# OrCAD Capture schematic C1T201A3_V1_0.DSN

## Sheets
1 002_POWER: size A; rev: V1.0; note: C1T201A3
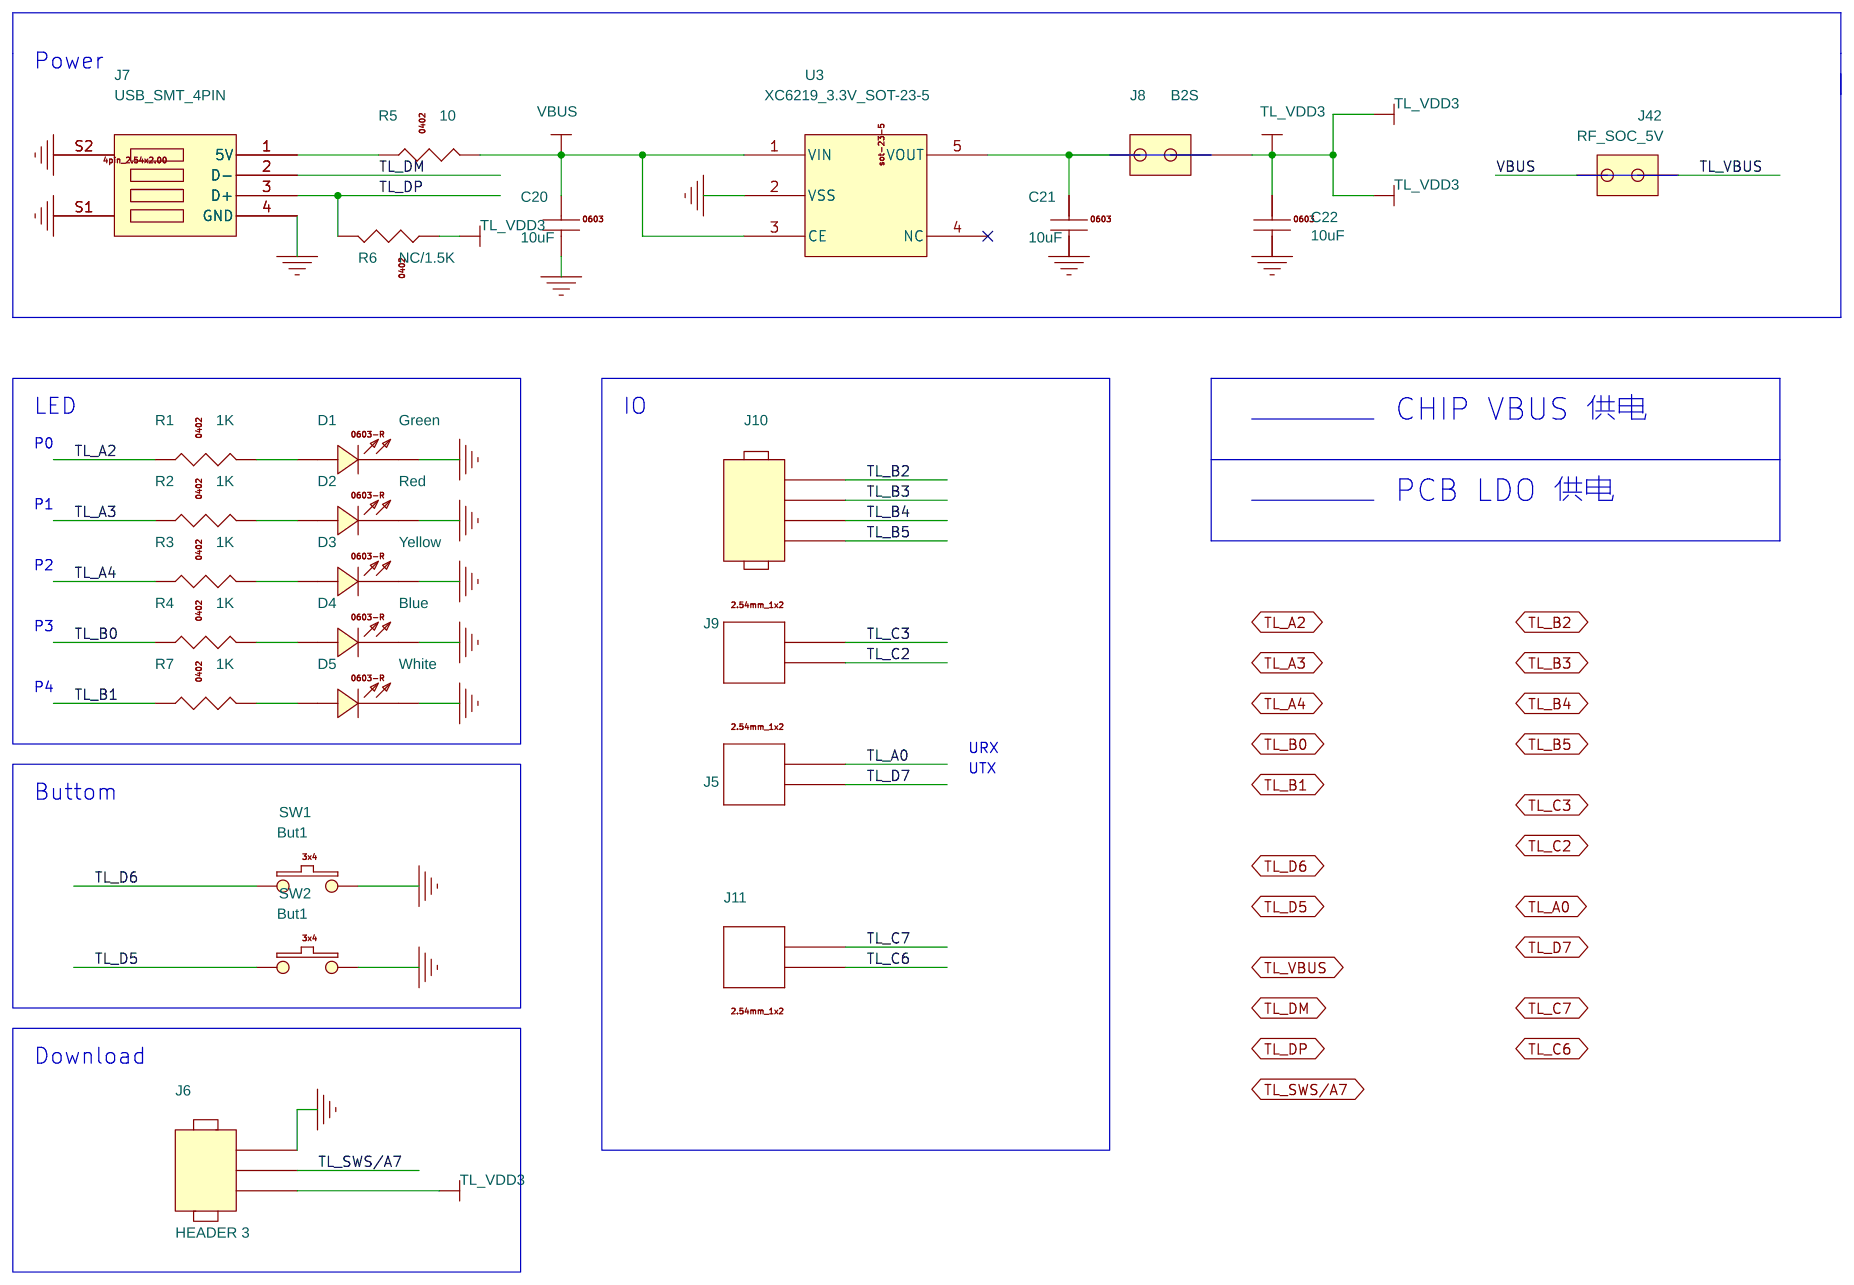
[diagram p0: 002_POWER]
2 000_NOTE: title: Telink-Semi
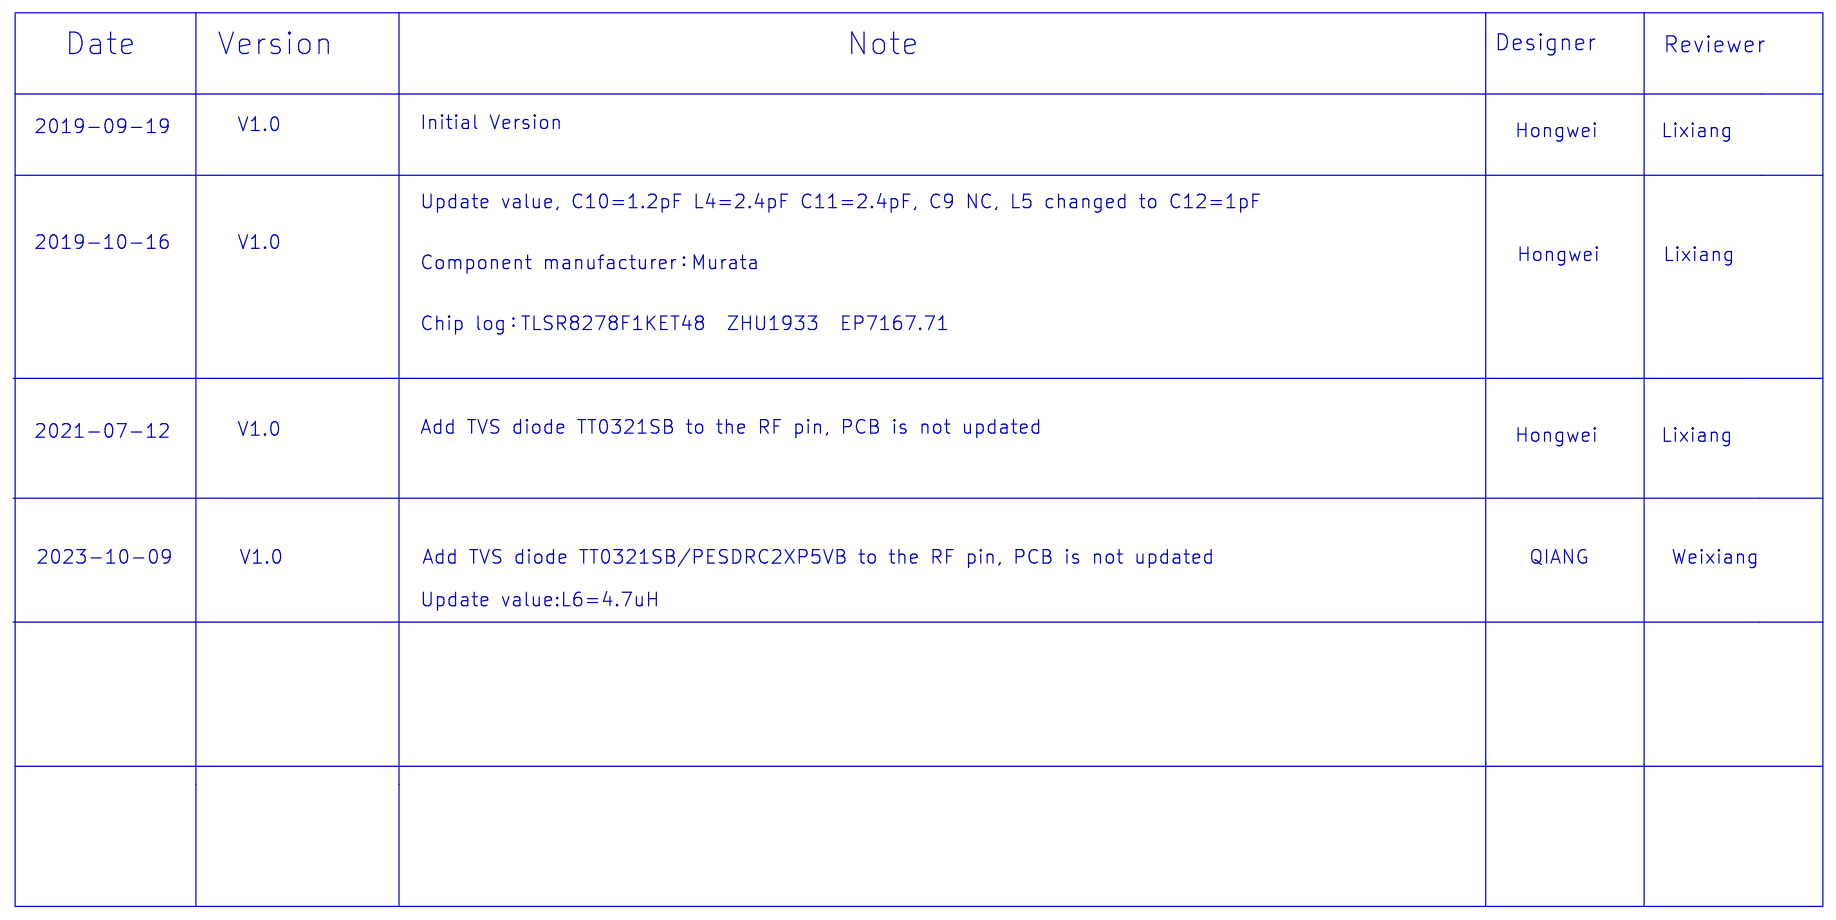
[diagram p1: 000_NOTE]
3 001_MAIN: size A4; title: Telink-Semi
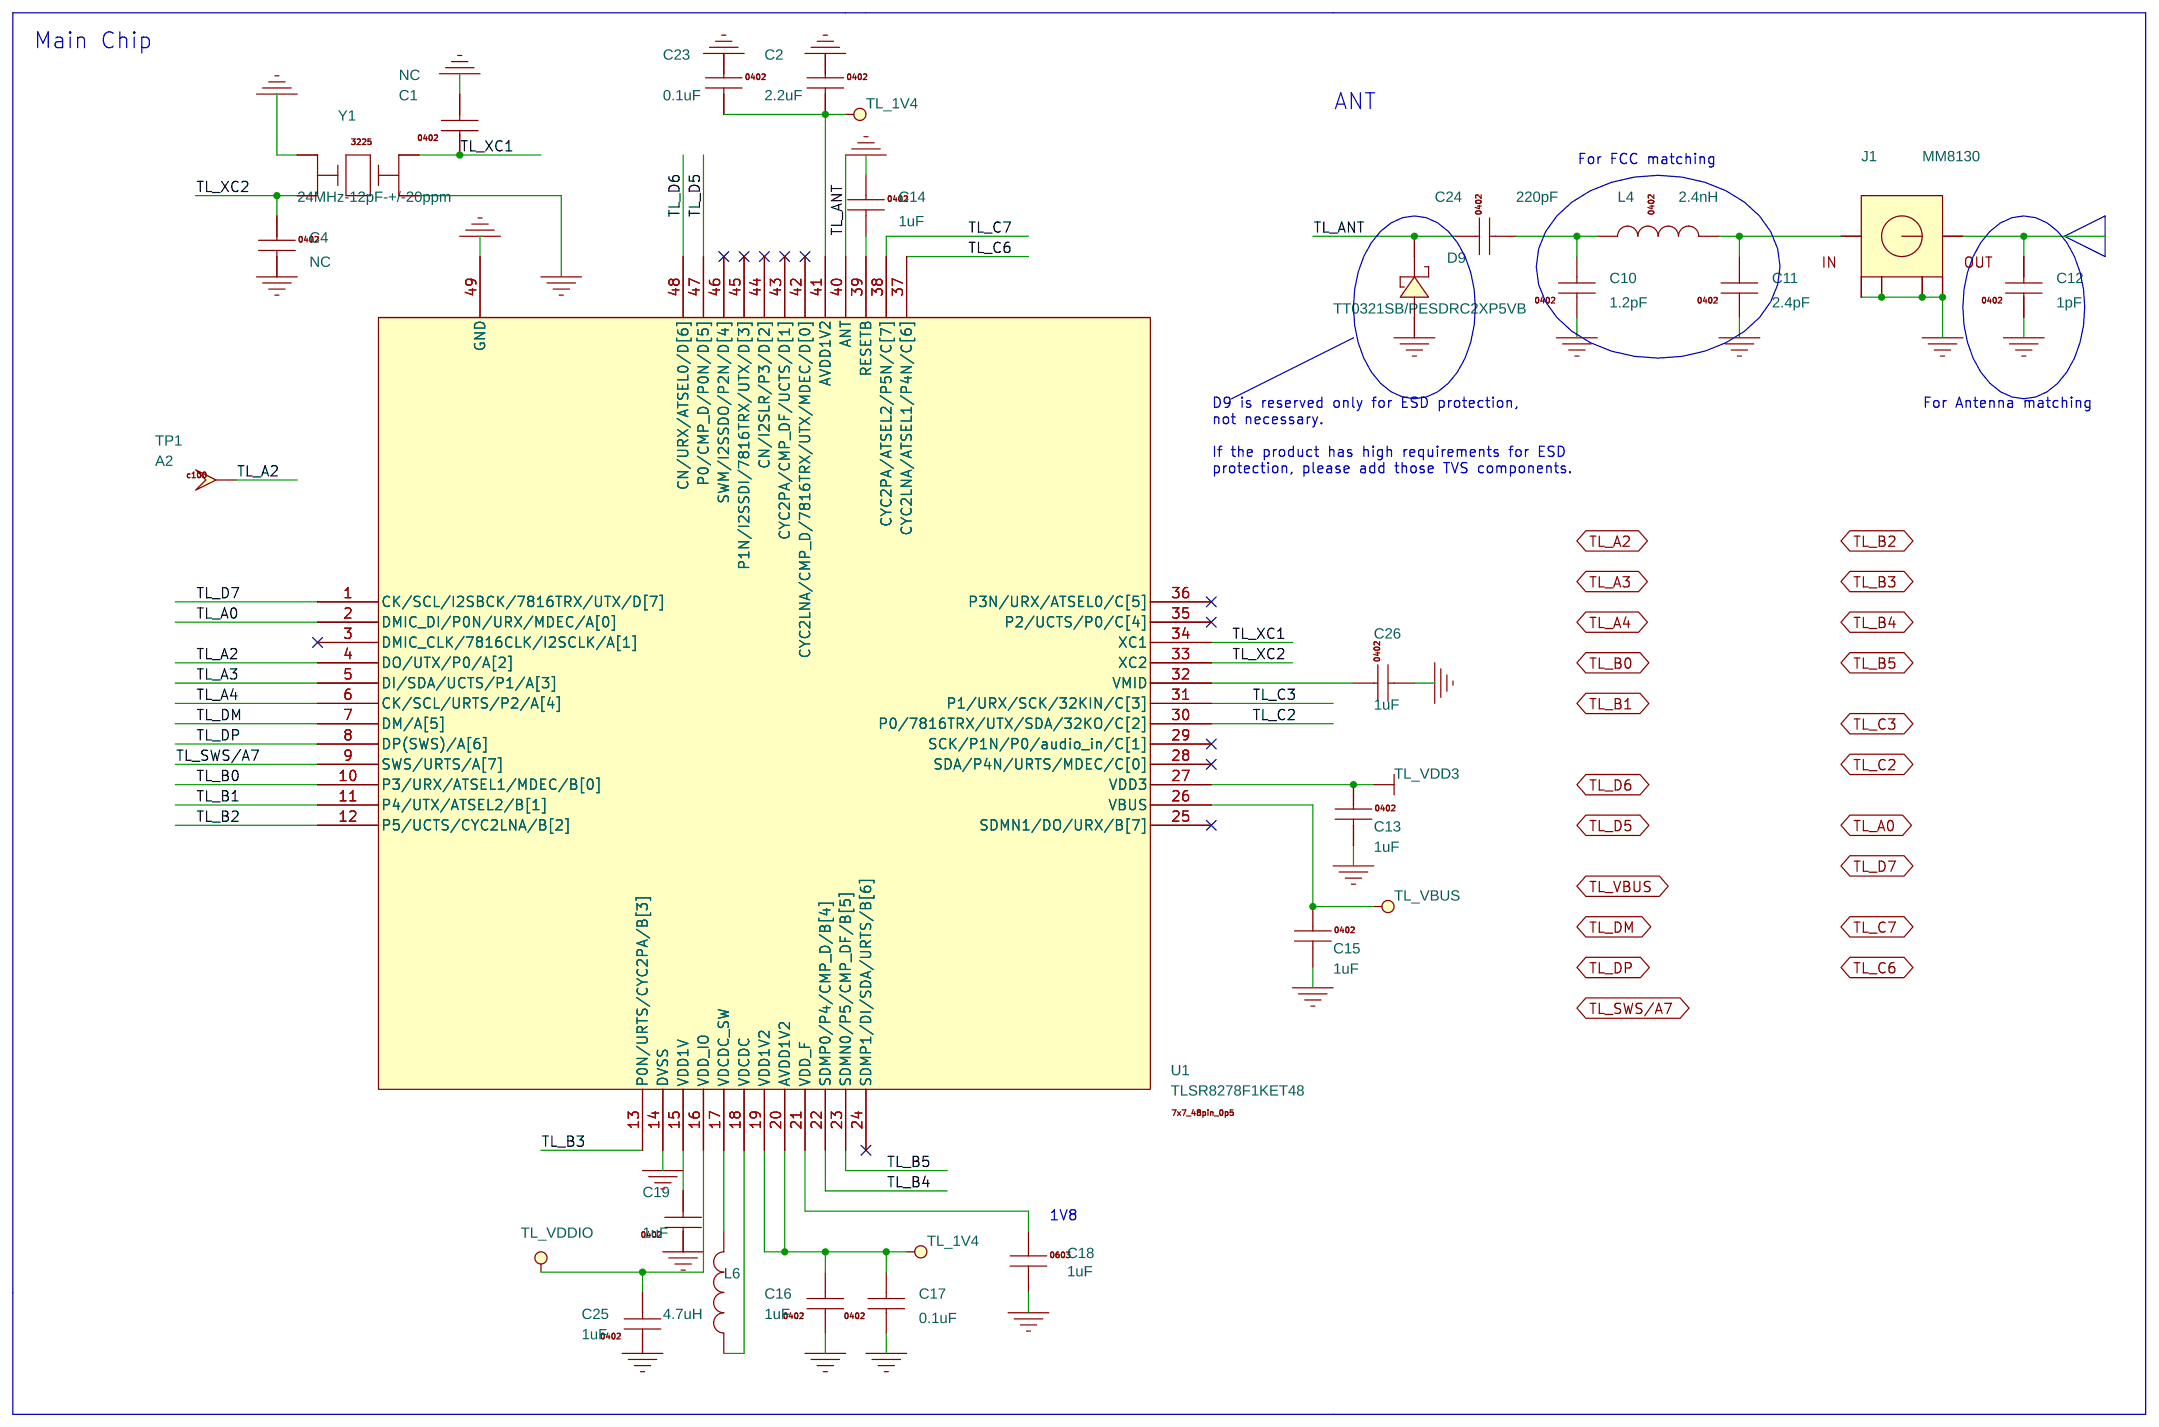
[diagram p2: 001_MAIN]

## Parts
sheet 001_MAIN
C1  NC  [0402]
C2  2.2uF  [0402]
C4  NC  [0402]
C10  1.2pF  [0402]
C11  2.4pF  [0402]
C12  1pF  [0402]
C13  1uF  [0402]
C14  1uF  [0402]
C15  1uF  [0402]
C16  1uF  [0402]
C17  0.1uF  [0402]
C18  1uF  [0402]
C19  1uF  [0402]
C23  0.1uF  [0402]
C24  220pF  [0402]
C25  1uF  [0402]
C26  1uF  [0402]
D9  TT0321SB/PESDRC2XP5VB  [SOD-123]
J1  MM8130  [MM8130-2600]
L4  2.4nH  [0402]
L6  4.7uH  [0805L]
TP1  A2  [TP100]
U1  TLSR8278F1KET48  [qfn_7x7_48pin_0p5_4p20x4p20]
Y1  24MHz-12pF-+/-20ppm  [osccc200x250x080]
sheet 002_POWER
C20  10uF  [0603C]
C21  10uF  [0603C]
C22  10uF  [0603C]
D1  Green  [0603-LED]
D2  Red  [0603-LED]
D3  Yellow  [0603-LED]
D4  Blue  [0603-LED]
D5  White  [0603-LED]
J5  CON_2.54mm_1x2  [hdr254f-1x2x850]
J6  HEADER 3  [hdr254m-1x3]
J7  USB_SMT_4PIN  [usb-m-4]
J8  B2S  [HDR254F-1X2X850]
J9  CON_2.54mm_1x2  [hdr254f-1x2x850]
J10  HEADER 4  [hdr254f-1x4x850]
J11  CON_2.54mm_1x2  [hdr254f-1x2x850]
J42  RF_SOC_5V  [HDR254F-1X2X850]
R1  1K  [0402]
R2  1K  [0402]
R3  1K  [0402]
R4  1K  [0402]
R5  10  [0402]
R6  NC/1.5K  [0402]
R7  1K  [0402]
SW1  But1  [butsmd2px4_00y3_00_nh]
SW2  But1  [butsmd2px4_00y3_00_nh]
U3  XC6219_3.3V_SOT-23-5  [sot-23-5]

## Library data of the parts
C1 C4 = C1005_NC
C2 C13-C15 C23 C24 C26 = C1005X5R1C104K
C10-C12 = C1608_NC_0
C16 C17 C19 C25 = C1005X5R1C105K
C18 C20-C22 = C1608X5R0J106M
D9 = DIODE_SCHOTTKY_0
J1 = MM8130
L4 = MLK1608_0
L6 = IND_0
TP1 = TestPad100
U1 = TLSR8278F1KET48_2
Y1 = OSC_25x32_4pin
D1-D5 = 0603D_Red
J5 J9 J11 = CON_2.54mm_1x2
J6 = HEADER_3
J7 = USB_SMT_1
J8 = B2S_0
J10 = HEADER_4
J42 = B2S_3: PAGE: POWER
R1-R4 R7 = RS0402K332JT
R5 R6 = RS0402K100JT
SW1 SW2 = SW2PIN_3x4
U3 = XC6219_1.3V_SOT-23-5

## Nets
3V3: C13.1 C22.1 C25.2 J6.3 J8.2 R6.1 U1.16(VDD_IO) U1.27(VDD3)
GND: C1.2 C2.1 C4.2 C10.1 C11.1 C12.1 C13.2 C14.1 C15.2 C16.1 C17.1 C18.2 C19.1 C20.2 C21.2 C22.2 C23.1 C25.1 C26.2 D1.C(CATHODE) D2.C(CATHODE) D3.C(CATHODE) D4.C(CATHODE) D5.C(CATHODE) D9.A(ANODE) J1.3 J1.4 J1.5 J1.6 J6.1 J7.4(GND) J7.S1 J7.S2 SW1.2 SW2.2 U1.14(DVSS) U1.49(GND) U3.2(VSS) Y1.2 Y1.4
VBUS: C20.1 J42.1 R5.2 U3.1(VIN) U3.3(CE)
TL_1V4: C2.2 C16.2 C17.2 C23.2 U1.19(VDD1V2) U1.20(AVDD1V2) U1.41(AVDD1V2)
TL_A0: U1.2(DMIC_DI/P0N/URX/MDEC/A[0])
TL_A0 (page 002_POWER): J5.1
TL_A2: TP1.1(TP) U1.4(DO/UTX/P0/A[2])
TL_A2 (page 002_POWER): R1.1
TL_A3: U1.5(DI/SDA/UCTS/P1/A[3])
TL_A3 (page 002_POWER): R2.1
TL_A4: U1.6(CK/SCL/URTS/P2/A[4])
TL_A4 (page 002_POWER): R3.1
TL_ANT: C24.1 D9.C(CATHODE) U1.40(ANT)
TL_B0: U1.10(P3/URX/ATSEL1/MDEC/B[0])
TL_B0 (page 002_POWER): R4.1
TL_B1: U1.11(P4/UTX/ATSEL2/B[1])
TL_B1 (page 002_POWER): R7.1
TL_B2: U1.12(P5/UCTS/CYC2LNA/B[2])
TL_B2 (page 002_POWER): J10.1
TL_B3: U1.13(P0N/URTS/CYC2PA/B[3])
TL_B3 (page 002_POWER): J10.2
TL_B4: U1.22(SDMP0/P4/CMP_D/B[4])
TL_B4 (page 002_POWER): J10.3
TL_B5: U1.23(SDMN0/P5/CMP_DF/B[5])
TL_B5 (page 002_POWER): J10.4
TL_C2: U1.30(P0/7816TRX/UTX/SDA/32KO/C[2])
TL_C2 (page 002_POWER): J9.2
TL_C3: U1.31(P1/URX/SCK/32KIN/C[3])
TL_C3 (page 002_POWER): J9.1
TL_C6: U1.37(CYC2LNA/ATSEL1/P4N/C[6])
TL_C6 (page 002_POWER): J11.1
TL_C7: U1.38(CYC2PA/ATSEL2/P5N/C[7])
TL_C7 (page 002_POWER): J11.2
TL_D5: U1.47(P0/CMP_D/P0N/D[5])
TL_D5 (page 002_POWER): SW2.1
TL_D6: U1.48(CN/URX/ATSEL0/D[6])
TL_D6 (page 002_POWER): SW1.1
TL_D7: U1.1(CK/SCL/I2SBCK/7816TRX/UTX/D[7])
TL_D7 (page 002_POWER): J5.2
TL_DM: U1.7(DM/A[5])
TL_DM (page 002_POWER): J7.2(D-)
TL_DP: U1.8(DP(SWS)/A[6])
TL_DP (page 002_POWER): J7.3(D+) R6.2
TL_SWS/A7: U1.9(SWS/URTS/A[7])
TL_SWS/A7 (page 002_POWER): J6.2
TL_VBUS: C15.1 U1.26(VBUS)
TL_VBUS (page 002_POWER): J42.2
TL_XC1: C1.1 U1.34(XC1) Y1.3
TL_XC2: C4.1 U1.33(XC2) Y1.1
N14798367: C18.1 U1.21(VDD_F)
N14798503: C19.2 U1.15(VDD1V)
N14803152: C10.2 C24.2 L4.1
N14803220: C11.2 J1.1 L4.2
N14803264: C12.2 J1.2
N14848024: L6.2 U1.17(VDCDC_SW)
N14849302: C26.1 U1.32(VMID)
N14850032: C14.2 U1.39(RESETB)
N14858611: C21.1 J8.1 U3.5(VOUT)
N14858615: J7.1(5V) R5.1
N14860106: D5.A(ANODE) R7.2
N14860310: D1.A(ANODE) R1.2
N14860350: D3.A(ANODE) R3.2
N14860358: D4.A(ANODE) R4.2
N14860454: D2.A(ANODE) R2.2
N14865099: L6.1 U1.18(VDCDC)

Not connected (* = marked no-connect by the designer): U1 3(DMIC_CLK/7816CLK/I2SCLK/A[1])* 24(SDMP1/DI/SDA/URTS/B[6])* 25(SDMN1/DO/URX/B[7])* 28(SDA/P4N/URTS/MDEC/C[0])* 29(SCK/P1N/P0/audio_in/C[1])* 35(P2/UCTS/P0/C[4])* 36(P3N/URX/ATSEL0/C[5])* 42(CYC2LNA/CMP_D/7816TRX/UTX/MDEC/D[0])* 43(CYC2PA/CMP_DF/UCTS/D[1])* 44(CN/I2SLR/P3/D[2])* 45(P1N/I2SSDI/7816TRX/UTX/D[3])* 46(SWM/I2SSDO/P2N/D[4])*; U3 4(NC)*

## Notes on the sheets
sheet 1
- Power
- LED
- IO
- CHIP VBUS 供电
- P0
- P1
- PCB LDO 供电
- P2
- P3
- P4
- URX
- UTX
- Buttom
- Download
sheet 2
- Date
- Version
- Note
- Designer
- Reviewer
- V1.0
- Initial Version
- 2019-09-19
- Hongwei
- Lixiang
- Update value, C10=1.2pF L4=2.4pF C11=2.4pF, C9 NC, L5 changed to C12=1pF
- 2019-10-16
- V1.0
- Component manufacturer：Murata
- Hongwei
- Lixiang
- Chip log：TLSR8278F1KET48  ZHU1933  EP7167.71
- 2021-07-12
- V1.0
- Add TVS diode TT0321SB to the RF pin, PCB is not updated
- Hongwei
- Lixiang
- 2023-10-09
- V1.0
- Add TVS diode TT0321SB/PESDRC2XP5VB to the RF pin, PCB is not updated
- QIANG
- Weixiang
- Update value:L6=4.7uH
sheet 3
- Main Chip
- ANT
- For FCC matching
- D9 is reserved only for ESD protection,
  not necessary.
  If the product has high requirements for ESD
  protection, please add those TVS components.
- For Antenna matching
- 1V8
